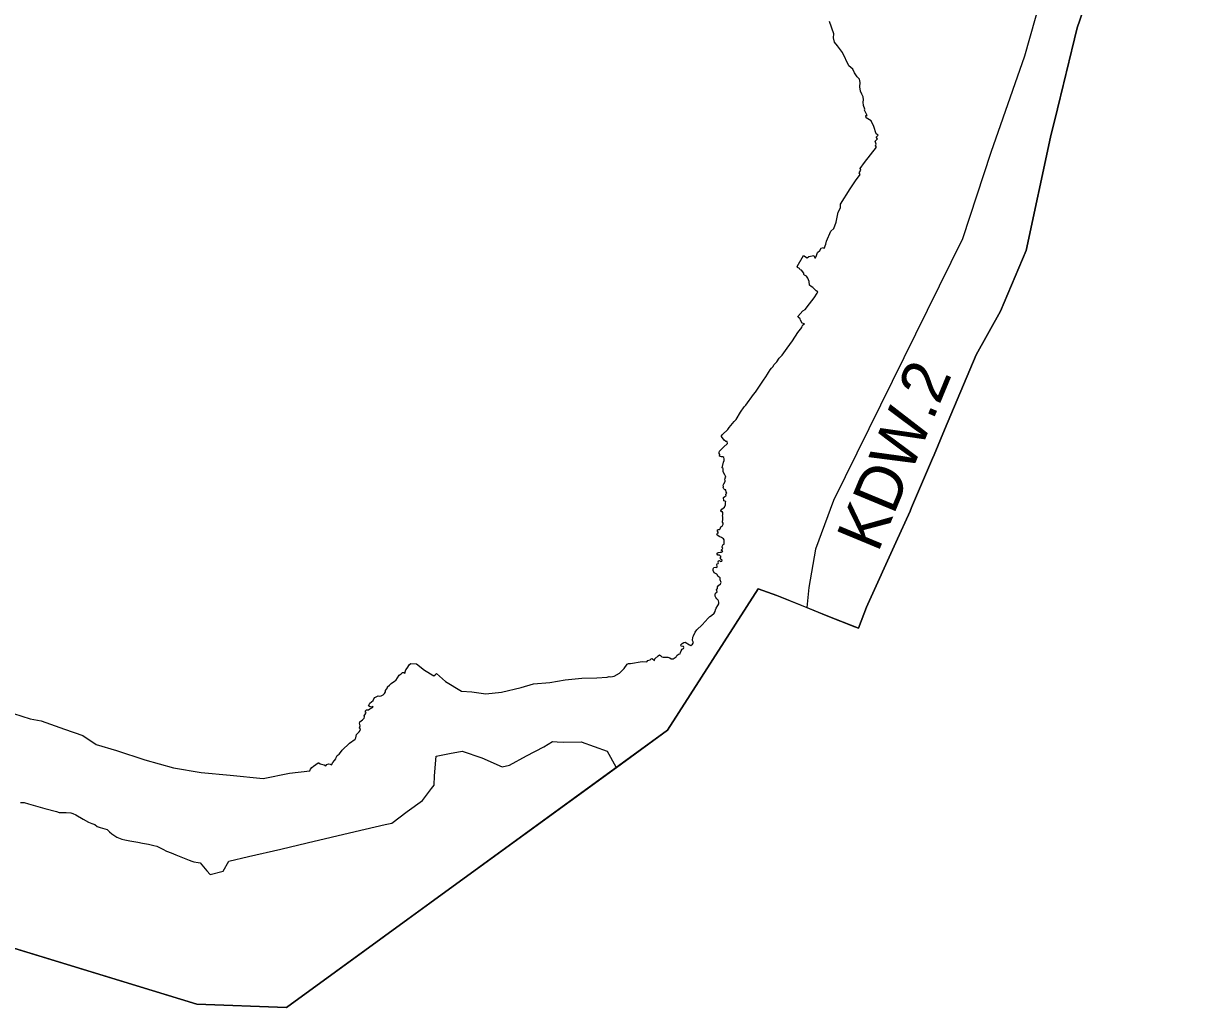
# Model space of a CAD drawing. Extents: x 7421614 to 7422630, y 5544623 to 5545754.
# Drawn here: x 7421910.5 to 7422166.2, y 5544623.3 to 5544838.1 of the extents above; entities that cross this region are included whole.
import ezdxf

# ---------------------------------------------------------------- set-up
doc = ezdxf.new("R2010")
doc.units = 0
for name, color, linetype in [('LIN_Granica Planu', 7, 'Continuous'), ('LIN_Linie Rozgraniczajace', 7, 'Continuous'), ('TXT_Oznaczenia Przeznaczenia', 7, 'Continuous')]:
    doc.layers.add(name, color=color, linetype=linetype)

msp = doc.modelspace()

# ---------------------------------------------------------------- linework, layer by layer
at = {"layer": 'LIN_Granica Planu'}
for p, q in [((7422108.81, 5544743.12), (7422104.27, 5544732.43)), ((7422104.27, 5544732.43), (7422103.93, 5544731.63)), ((7422070.78, 5544714.69), (7422051.02, 5544683.87)), ((7422074.84, 5544713.25), (7422070.78, 5544714.69)), ((7422086.01, 5544708.77), (7422074.84, 5544713.25)), ((7422092.66, 5544706.11), (7422086.01, 5544708.77)), ((7422094.41, 5544710.72), (7422092.66, 5544706.11)), ((7421948.36, 5544624.06), (7421835.68, 5544658.51))]:
    msp.add_line(p, q, dxfattribs=at)
for points in [[(7422166.21, 5544920.42), (7422162.02, 5544900.44), (7422159.37, 5544891.82), (7422140.37, 5544837.11), (7422136.08, 5544819.42), (7422134.53, 5544813.25), (7422129.23, 5544788.52), (7422123.65, 5544775.25), (7422118.35, 5544765.76), (7422111.44, 5544749.36), (7422109.16, 5544743.94), (7422108.81, 5544743.12)], [(7422103.93, 5544731.63), (7422100.83, 5544724.83), (7422094.71, 5544711.38), (7422094.41, 5544710.72)], [(7422051.02, 5544683.87), (7421967.91, 5544623.35), (7421948.36, 5544624.06)]]:
    msp.add_lwpolyline(points, dxfattribs=at)
at = {"layer": 'LIN_Linie Rozgraniczajace'}
for points in [[(7422081.44, 5544710.61), (7422086.01, 5544708.77), (7422091.86, 5544706.43), (7422092.66, 5544706.11), (7422094.41, 5544710.72), (7422094.71, 5544711.38), (7422100.83, 5544724.83), (7422103.93, 5544731.63), (7422104.27, 5544732.43), (7422108.81, 5544743.12), (7422109.16, 5544743.94), (7422111.44, 5544749.36), (7422118.35, 5544765.76), (7422123.65, 5544775.25), (7422129.23, 5544788.52), (7422134.53, 5544813.25), (7422136.08, 5544819.42), (7422137.46, 5544825.1), (7422140.37, 5544837.11), (7422159.37, 5544891.82), (7422162.02, 5544900.44), (7422166.21, 5544920.42)], [(7422147.03, 5544888.89), (7422136.01, 5544856.12), (7422128.91, 5544830.94), (7422121.52, 5544809.87), (7422115.38, 5544791.06), (7422087.21, 5544733.94), (7422083.31, 5544723.39), (7422081.85, 5544714.99), (7422081.44, 5544710.61)], [(7421908.35, 5544687.47), (7421911.99, 5544686.34), (7421914.41, 5544685.87), (7421919.47, 5544684.06), (7421923.48, 5544682.73), (7421926.34, 5544680.75), (7421930.79, 5544679.46), (7421936.97, 5544677.43), (7421943.21, 5544675.63), (7421949.3, 5544674.66), (7421955.59, 5544674.06), (7421962.8, 5544673.29), (7421968.53, 5544674.46), (7421972.96, 5544674.96), (7421973.15, 5544675.36), (7421973.41, 5544675.71), (7421973.77, 5544676.04), (7421974.78, 5544676.76), (7421974.96, 5544676.72), (7421975.23, 5544676.5), (7421976.13, 5544676.28), (7421976.47, 5544676.11), (7421976.73, 5544676.36), (7421977.03, 5544676.49), (7421977.41, 5544676.43), (7421977.74, 5544676.29), (7421978.01, 5544676.79), (7421978.4, 5544677.22), (7421978.67, 5544677.6), (7421978.7, 5544677.93), (7421978.97, 5544678.34), (7421979.36, 5544678.61), (7421979.67, 5544678.97), (7421980.01, 5544679.49), (7421981.63, 5544681), (7421982.85, 5544681.88), (7421983, 5544682.2), (7421983.18, 5544682.91), (7421983.76, 5544683.47), (7421983.95, 5544683.81), (7421984.02, 5544684.12), (7421983.82, 5544684.38), (7421983.96, 5544684.79), (7421983.8, 5544685.37), (7421983.88, 5544685.67), (7421984.5, 5544686.12), (7421984.81, 5544686.48), (7421984.91, 5544686.8), (7421984.85, 5544687.02), (7421985.12, 5544687.42), (7421985.24, 5544687.73), (7421985.12, 5544687.72), (7421985.16, 5544688.09), (7421985.37, 5544688.27), (7421985.75, 5544688.29), (7421986.07, 5544688.53), (7421986.81, 5544688.87), (7421986.76, 5544689.02), (7421986.44, 5544688.92), (7421986.14, 5544688.96), (7421985.77, 5544689.16), (7421986.09, 5544689.79), (7421986.8, 5544690.37), (7421986.95, 5544690.69), (7421987.2, 5544690.99), (7421987.87, 5544691.34), (7421988.18, 5544691.25), (7421988.56, 5544691.34), (7421988.96, 5544691.59), (7421989.25, 5544691.87), (7421989.5, 5544692.2), (7421989.51, 5544692.5), (7421989.94, 5544693.12), (7421989.96, 5544693.29), (7421990.36, 5544693.66), (7421990.7, 5544694.06), (7421991.42, 5544694.57), (7421991.78, 5544694.73), (7421992.51, 5544695.85), (7421992.88, 5544696.17), (7421993.22, 5544696.42), (7421993.49, 5544696.47), (7421993.7, 5544696.33), (7421993.83, 5544696.54), (7421993.78, 5544696.69), (7421993.94, 5544697.04), (7421994.23, 5544697.41), (7421994.73, 5544698.22), (7421995.02, 5544698.42), (7421996.27, 5544698.37), (7421997.97, 5544696.94), (7422000.02, 5544695.69), (7422000.35, 5544695.93), (7422000.6, 5544696.2), (7422002.6, 5544694.47), (7422006.08, 5544692.34), (7422008.33, 5544692.23), (7422011.37, 5544691.81), (7422014.79, 5544692.18), (7422019.08, 5544693.19), (7422021.8, 5544693.94), (7422025.33, 5544694.25), (7422028.71, 5544694.88), (7422032.31, 5544695.19), (7422035.62, 5544695.3), (7422037.83, 5544695.43), (7422038.3, 5544695.55), (7422038.67, 5544695.47), (7422039.38, 5544695.67), (7422040.52, 5544696.32), (7422041.54, 5544697.32), (7422042.2, 5544698.23), (7422042.53, 5544698.41), (7422042.93, 5544698.44), (7422045.5, 5544698.83), (7422046.47, 5544698.78), (7422046.7, 5544699.06), (7422047.24, 5544699.19), (7422047.46, 5544699.42), (7422047.68, 5544699.5), (7422048.19, 5544699.09), (7422048.28, 5544699.44), (7422048.95, 5544700.09), (7422049.25, 5544700.28), (7422049.52, 5544700.13), (7422049.78, 5544699.87), (7422050.09, 5544699.78), (7422051.1, 5544699.8), (7422051.51, 5544699.63), (7422051.82, 5544699.44), (7422052.23, 5544699.4), (7422052.91, 5544699.88), (7422053.05, 5544700.14), (7422053.39, 5544700.44), (7422053.74, 5544700.5), (7422053.84, 5544700.83), (7422054.03, 5544701.2), (7422054.23, 5544701.52), (7422054.48, 5544701.66), (7422054.61, 5544701.89), (7422054.48, 5544702.09), (7422054.03, 5544702.21), (7422053.95, 5544702.47), (7422054.22, 5544702.81), (7422054.57, 5544703.01), (7422054.86, 5544703.09), (7422055.8, 5544702.47), (7422056.11, 5544702.33), (7422056.5, 5544702.6), (7422056.66, 5544702.96), (7422056.46, 5544703.45), (7422056.52, 5544704.13), (7422056.69, 5544704.43), (7422057.04, 5544705.28), (7422057.4, 5544705.74), (7422058.58, 5544706.88), (7422059.88, 5544708.3), (7422060.28, 5544708.67), (7422060.62, 5544708.89), (7422061.21, 5544709.36), (7422061.38, 5544709.73), (7422061.46, 5544710.12), (7422061.61, 5544710.49), (7422062.02, 5544711.09), (7422062.19, 5544711.44), (7422062.23, 5544711.82), (7422062.16, 5544712.07), (7422062.08, 5544712.24), (7422061.79, 5544712.51), (7422061.57, 5544712.82), (7422061.42, 5544713.09), (7422061.41, 5544713.48), (7422061.5, 5544713.75), (7422061.87, 5544714.02), (7422061.69, 5544714.48), (7422061.95, 5544714.78), (7422061.95, 5544715.16), (7422062.12, 5544715.42), (7422062.56, 5544715.77), (7422062.69, 5544716.08), (7422062.47, 5544716.66), (7422062.49, 5544717.1), (7422062.1, 5544717.42), (7422061.78, 5544717.93), (7422061.16, 5544718.19), (7422061.01, 5544718.71), (7422060.99, 5544719.09), (7422061.12, 5544719.32), (7422061.41, 5544719.42), (7422061.75, 5544719.39), (7422061.86, 5544719.6), (7422061.79, 5544719.98), (7422061.88, 5544720.18), (7422062.08, 5544720.26), (7422062.17, 5544720.38), (7422062.05, 5544720.61), (7422062.11, 5544720.78), (7422062.33, 5544720.86), (7422062.46, 5544720.84), (7422062.6, 5544720.65), (7422062.86, 5544720.75), (7422062.91, 5544720.94), (7422062.71, 5544721.09), (7422062.6, 5544721.26), (7422062.57, 5544721.57), (7422062.72, 5544721.77), (7422062.57, 5544721.83), (7422062.39, 5544722.05), (7422061.96, 5544722.06), (7422061.82, 5544722.28), (7422061.86, 5544722.5), (7422062.09, 5544722.63), (7422062.52, 5544722.71), (7422062.73, 5544722.7), (7422063.07, 5544722.93), (7422062.76, 5544723.08), (7422062.79, 5544723.24), (7422063.04, 5544723.4), (7422063.11, 5544723.54), (7422062.94, 5544723.75), (7422062.92, 5544723.94), (7422063.19, 5544724.35), (7422063.34, 5544724.45), (7422063.37, 5544725.4), (7422063.25, 5544725.58), (7422062.76, 5544725.93), (7422062.45, 5544726.04), (7422061.87, 5544726.42), (7422061.81, 5544726.58), (7422061.94, 5544726.81), (7422062.14, 5544726.93), (7422061.93, 5544727.27), (7422061.95, 5544727.54), (7422062.11, 5544727.66), (7422062.35, 5544727.62), (7422062.48, 5544727.81), (7422062.62, 5544728.23), (7422062.93, 5544728.37), (7422063.16, 5544728.82), (7422063.19, 5544729.03), (7422063.03, 5544729.25), (7422063, 5544729.53), (7422063.09, 5544729.69), (7422063.1, 5544730.41), (7422063.01, 5544730.57), (7422063.09, 5544730.95), (7422063.07, 5544731.18), (7422063.11, 5544731.39), (7422062.99, 5544731.48), (7422062.74, 5544731.52), (7422062.63, 5544731.75), (7422062.84, 5544732.06), (7422063.48, 5544732.55), (7422063.7, 5544733.01), (7422063.66, 5544733.49), (7422063.71, 5544733.75), (7422063.33, 5544733.9), (7422063.25, 5544734.63), (7422063.51, 5544734.86), (7422063.66, 5544734.9), (7422063.84, 5544735.01), (7422063.73, 5544735.25), (7422063.96, 5544735.56), (7422063.78, 5544735.78), (7422063.74, 5544736.28), (7422063.52, 5544736.32), (7422063.28, 5544736.55), (7422063.19, 5544736.82), (7422063.23, 5544737.06), (7422063.19, 5544737.35), (7422063.27, 5544737.62), (7422063.58, 5544738.14), (7422063.61, 5544738.34), (7422063.54, 5544738.66), (7422063.58, 5544738.86), (7422063.71, 5544739.05), (7422063.65, 5544739.29), (7422063.49, 5544739.56), (7422063.19, 5544740.25), (7422063.19, 5544740.65), (7422063.13, 5544740.93), (7422062.97, 5544741.13), (7422063.21, 5544742.34), (7422063.35, 5544742.7), (7422063.37, 5544743.07), (7422063.32, 5544743.36), (7422063.08, 5544743.47), (7422062.8, 5544743.49), (7422062.34, 5544743.64), (7422062.41, 5544744), (7422062.28, 5544744.24), (7422062.28, 5544744.42), (7422062.37, 5544744.7), (7422063.23, 5544745.62), (7422064.09, 5544746.42), (7422064.01, 5544746.84), (7422063.75, 5544746.87), (7422063.41, 5544747.1), (7422062.81, 5544747.91), (7422062.81, 5544748.11), (7422063.02, 5544748.39), (7422064.2, 5544749.45), (7422064.46, 5544749.88), (7422065.55, 5544751.23), (7422065.98, 5544751.61), (7422066.92, 5544753.24), (7422067.75, 5544754.39), (7422068.08, 5544754.77), (7422069.77, 5544757.09), (7422070.2, 5544757.62), (7422071.55, 5544759.59), (7422071.95, 5544760.24), (7422072.49, 5544760.94), (7422072.86, 5544761.54), (7422073.03, 5544761.93), (7422073.41, 5544762.49), (7422073.7, 5544762.87), (7422073.98, 5544763.15), (7422074.29, 5544763.62), (7422074.85, 5544764.22), (7422075.35, 5544765), (7422076.04, 5544765.71), (7422077.11, 5544767.23), (7422078.29, 5544768.78), (7422079.41, 5544770.6), (7422080.3, 5544771.7), (7422080.37, 5544772.01), (7422080.55, 5544772.27), (7422080.89, 5544772.48), (7422080.4, 5544772.65), (7422080.03, 5544773.29), (7422079.95, 5544773.59), (7422079.53, 5544773.95), (7422079.47, 5544774.08), (7422080.56, 5544775.37), (7422081.02, 5544775.65), (7422082.01, 5544776.88), (7422083.02, 5544778.18), (7422083.69, 5544779.19), (7422083.79, 5544779.49), (7422083.46, 5544779.72), (7422082.7, 5544780.45), (7422082.35, 5544780.66), (7422082.02, 5544780.98), (7422081.93, 5544781.76), (7422081.64, 5544782.48), (7422081.3, 5544782.88), (7422080.9, 5544783.11), (7422080.74, 5544783.26), (7422080.77, 5544783.59), (7422080.28, 5544784.21), (7422079.97, 5544784.33), (7422079.78, 5544784.6), (7422079.37, 5544784.8), (7422079.28, 5544785.02), (7422080.7, 5544787.4), (7422081.45, 5544786.94), (7422081.87, 5544787.21), (7422082.91, 5544787.42), (7422083.14, 5544786.91), (7422083.31, 5544786.93), (7422083.55, 5544787.4), (7422083.71, 5544788.05), (7422084.25, 5544788.48), (7422084.55, 5544789.02), (7422085.03, 5544789.17), (7422085.21, 5544788.93), (7422085.59, 5544789.87), (7422085.73, 5544790.54), (7422086.65, 5544792.73), (7422087.33, 5544793.34), (7422087.78, 5544794.68), (7422088.24, 5544796.88), (7422088.78, 5544797.79), (7422088.76, 5544798.64), (7422090.88, 5544802), (7422092.03, 5544803.72), (7422093.01, 5544805.06), (7422092.85, 5544805.44), (7422093.22, 5544806.03), (7422093.08, 5544806.42), (7422093.98, 5544807.72), (7422096.58, 5544811.08), (7422096.42, 5544811.35), (7422096.56, 5544811.68), (7422096.3, 5544812.35), (7422096.79, 5544812.85), (7422096.55, 5544813.22), (7422096.95, 5544813.65), (7422096.53, 5544813.96), (7422096.05, 5544815.56), (7422095.47, 5544816.83), (7422094.36, 5544817.49), (7422094.29, 5544817.94), (7422094.56, 5544817.99), (7422094, 5544819.1), (7422094.03, 5544819.37), (7422093.79, 5544820.13), (7422093.7, 5544820.89), (7422093.78, 5544821.38), (7422093.67, 5544822.01), (7422093.38, 5544822.59), (7422093.14, 5544823.25), (7422092.98, 5544824.24), (7422093.05, 5544825.17), (7422092.92, 5544825.92), (7422092.38, 5544826.4), (7422091.83, 5544827.29), (7422091.42, 5544828.1), (7422090.55, 5544828.83), (7422089.18, 5544831.68), (7422088.09, 5544833.19), (7422087.42, 5544833.99), (7422087.22, 5544834.94), (7422087.28, 5544835.8), (7422086.36, 5544838.46)], [(7422039.86, 5544675.74), (7422051.02, 5544683.87), (7422070.78, 5544714.69), (7422074.84, 5544713.25), (7422078.87, 5544711.64), (7422081.44, 5544710.61)], [(7421725.94, 5544704.1), (7421764.74, 5544677.85), (7421835.68, 5544658.51), (7421860.75, 5544650.85), (7421948.36, 5544624.06), (7421967.91, 5544623.35), (7421979.89, 5544632.08), (7421999.46, 5544646.33), (7422039.86, 5544675.74)], [(7421909.83, 5544668.08), (7421910.66, 5544668.07), (7421911.6, 5544667.81), (7421912.63, 5544667.52), (7421915.17, 5544666.81), (7421917.71, 5544666.1), (7421918.3, 5544665.88), (7421919.86, 5544665.89), (7421920.83, 5544665.81), (7421921.28, 5544665.67), (7421921.92, 5544665.43), (7421923.57, 5544664.48), (7421924.71, 5544663.83), (7421925.46, 5544663.48), (7421926.08, 5544663.25), (7421926.62, 5544662.87), (7421927.25, 5544662.66), (7421928.78, 5544662.16), (7421929.28, 5544661.71), (7421929.78, 5544661.27), (7421930.87, 5544660.51), (7421931.95, 5544660.12), (7421932.66, 5544659.91), (7421933.69, 5544659.71), (7421935.46, 5544659.4), (7421936.46, 5544659.22), (7421937.77, 5544659.02), (7421938.92, 5544658.72), (7421939.58, 5544658.55), (7421940.93, 5544657.87), (7421941.69, 5544657.49), (7421942.71, 5544657.08), (7421943.74, 5544656.66), (7421946.69, 5544655.51), (7421947.26, 5544655.29), (7421947.66, 5544655.14), (7421948.59, 5544655.03), (7421949.04, 5544654.9), (7421950.55, 5544653.18), (7421951.24, 5544652.39), (7421954.07, 5544653.08), (7421955.31, 5544655.28), (7421959.61, 5544656.31), (7421966.66, 5544657.93), (7421972.37, 5544659.25), (7421982.89, 5544661.76), (7421989.44, 5544663.26), (7421990.84, 5544663.58), (7421994.23, 5544666.09), (7421997.55, 5544668.55), (7421999.5, 5544671.12), (7422000.09, 5544671.89), (7422000.2, 5544673.93), (7422000.54, 5544678.22), (7422003.48, 5544678.79), (7422006.23, 5544679.31), (7422010.48, 5544677.84), (7422014.96, 5544675.88), (7422016.56, 5544676.21), (7422020.22, 5544678.25), (7422024.01, 5544680.26), (7422025.96, 5544681.39), (7422026.96, 5544681.33), (7422028.4, 5544681.25), (7422032.21, 5544681.29), (7422037.82, 5544679.27), (7422039.77, 5544675.9), (7422039.86, 5544675.74)]]:
    msp.add_lwpolyline(points, dxfattribs=at)

# ---------------------------------------------------------------- texts
at = {"layer": 'TXT_Oznaczenia Przeznaczenia'}
msp.add_text('KDW.2', height=10, rotation=67.4821, dxfattribs=at).set_placement((7422096.91, 5544722.4))

doc.saveas('drawing.dxf')
